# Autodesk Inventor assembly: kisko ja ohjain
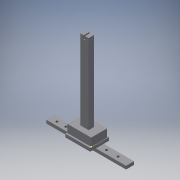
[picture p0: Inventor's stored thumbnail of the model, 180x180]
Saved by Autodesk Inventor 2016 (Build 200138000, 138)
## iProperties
Created: 2016-02
Part Number: kisko ja ohjain
Document SubType Name: Assembly
Designer: Juha-Pekka
Author: Juha-Pekka
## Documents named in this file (3)
- C:\Users\Juha-Pekka\Desktop\Assignment2\kisko ja ohjain.iam
- C:\Users\Juha-Pekka\Desktop\Assignment2\rail.ipt
- C:\Users\Juha-Pekka\Desktop\Assignment2\pilari.ipt
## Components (2 placed, 2 different names)
1. rail:1
2. pilari:1
